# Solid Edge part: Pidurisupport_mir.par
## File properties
Author: Türk
Template: Iso Part.par
Last saved by: Türk
Revision: 2
Application: Solid Edge
Accuracy: 0,990
Username: Türk
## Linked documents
Pidurisupport.par
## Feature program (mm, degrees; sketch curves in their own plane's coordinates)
part copy "CopiedPart_1"
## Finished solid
Body 1: solid body, 63 faces, 128 edges, 66 vertices.
  Faces by surface: plane 27, cylinder 22, cone 13, spline 1
  Edges by curve: circle 64, line 40, intersection 10, ellipse 8, curve on surface 6
Bounding box of the edges (mm; curved faces can reach further): 96.748 x 162.000 x 85.456, from (-27.7472, -80, -26.5) to (69.0008, 82, 58.9555).
Cylindrical faces by radius (mm): R4 x8, R5 x2, R10 x6, R12.5 x3, R60 x2, R100 x1
Conical faces (half-angle, radius in mm at the cone's reference point): 45 deg R5 x2, 45 deg R12.5 x6, 45 deg R60 x1, 45 deg R61 x2, 45 deg R99 x1, 45 deg R100 x1
Planar faces by outward normal: +x 2, +y 8, -y 7, -z 2, oblique 8
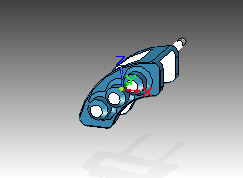
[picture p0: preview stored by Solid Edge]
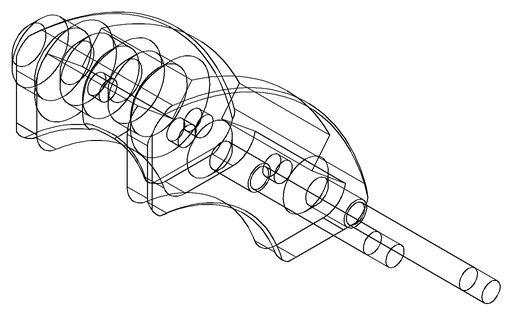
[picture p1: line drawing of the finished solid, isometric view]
